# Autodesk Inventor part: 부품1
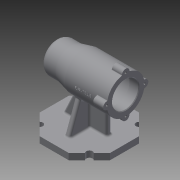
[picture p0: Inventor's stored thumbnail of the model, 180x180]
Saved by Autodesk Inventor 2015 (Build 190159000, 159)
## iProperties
Created: 2019-12
Part Number: 부품1
Material: 일반
Document SubType Name: Modeling
Designer: now
Density: 1 g/cm^3
Appearance: 기본값
Author: now
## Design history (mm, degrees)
sketch "스케치1" dims "d0" = 112
  geometry: L1 (23.196, -56)-(-23.196, -56); L2 (-23.196, -56)-(-56, -23.196); L3 (-56, -23.196)-(-56, 23.196); L4 (-56, 23.196)-(-23.196, 56); L5 (-23.196, 56)-(23.196, 56); L6 (23.196, 56)-(56, 23.196); L7 (56, 23.196)-(56, -23.196); L8 (56, -23.196)-(23.196, -56); 6 further points
  constraints: 16 end point, 3 coincident, 3 midpoint, 1 horizontal alignment, 1 vertical alignment, 20 other
extrude "돌출1" new body sketch "스케치1" distance "d1" = 10; taper "d2" = 0 deg
sketch "스케치2"
  geometry: L1 (23.196, -56)-(56, -23.196) reference; L2 (-23.196, 56)-(-56, 23.196) reference; L3 (-56, -23.196)-(-23.196, -56) reference; L4 (23.196, 56)-(56, 23.196) reference; 5 further points
  constraints: 4 midpoint
hole "구멍1" sketch "스케치2" at (-39.598, 39.598), (-39.598, -39.598), (39.598, 39.598), (39.598, -39.598) diameter "d3" = 10; stored, may be unused: countersink angle "d7" = 90 deg, drill point angle "d9" = 118 deg; dims "d4" = 6, "d5" = 4, "d6" = 2, "d8" = 8
sketch "스케치3"
  geometry: L1 (23.196, 56)-(-23.196, 56) reference; L2 (-56, 23.196)-(-56, -23.196) reference; L3 (-23.196, -56)-(23.196, -56) reference; L4 (56, -23.196)-(56, 23.196) reference; L5 (-38, 4)-(31, 4); L6 (31, 4)-(31, -4); L7 (31, -4)-(-38, -4); L8 (-38, -4)-(-38, 4); L9 (-4, 36)-(4, 36); L10 (4, 36)-(4, -36); L11 (4, -36)-(-4, -36); L12 (-4, -36)-(-4, 36); 1 further point
  constraints: 16 end point, 4 parallel, 2 horizontal, 2 perpendicular
  dimensions: "d10" = 8 distance of L9.start L9.end; "d11" = 8 distance of L5.end L6.end; "d12" = 4 distance from line of point (0, 0) L5; "d13" = 4 distance from line of point (0, 0) L12; "d14" = 18 distance between parallel lines of L2 L8; "d15" = 25 distance between parallel lines of L4 L6; "d16" = 20 distance between parallel lines of L1 L9; "d17" = 20 distance between parallel lines of L3 L11
extrude "돌출2" join sketch "스케치3" distance "d18" = 70; taper "d19" = 0 deg
feature "면 기울기1" dims angle "d20" = 25 deg
feature "면 기울기2" dims angle "d21" = 20 deg
sketch "스케치4"
  geometry: L1 (56, 0)-(-56, 0) reference; L2 (-56, 0)-(-56, 10) reference; L3 (-56, 10)-(-31, 10) reference; L4 (-31, 10)-(-31, 80) reference; L5 (-31, 80)-(5.358, 80) reference; L6 (5.358, 80)-(38, 10) reference; L7 (38, 10)-(56, 10) reference; L8 (56, 10)-(56, 0) reference; L9 (54, 80)-(-58, 80); L10 (-58, 80)-(-58, 110); L11 (-58, 110)-(9, 110); L12 (9, 110)-(29, 105); L13 (29, 105)-(54, 105); L14 (54, 105)-(54, 80); 1 further point
  constraints: 12 end point, 3 horizontal, 2 vertical
  dimensions: "d22" = 30 distance between parallel lines of L9 L11; "d23" = 80 distance between parallel lines of L1 L9; "d24" = 45 horizontal distance of L11.end L13.end; "d25" = 112 distance between parallel lines of L10 L14; "d26" = 25 distance of L13.end L12.end; "d27" = 25 distance of L13.end L9.start
revolve "회전1" sketch "스케치4" stored, may be unused: angle "d28" = 90 deg
sketch "스케치5"
  geometry: C1 r 6 at (-30, 0); C2 r 6 at (0, 30); C3 r 6 at (30, 0); C4 r 6 at (0, -30); A1 r 30 centre (0, 0) between (-30, 0) and (0, 30) reference; 1 further point
  constraints: 4 centre point, 4 point on circle
  dimensions: "d29" = 12 diameter of C1; "d30" = 12 diameter of C2; "d31" = 12 diameter of C3; "d32" = 12 diameter of C4
extrude "돌출3" join sketch "스케치5" distance "d33" = 16; taper "d34" = 0 deg
sketch "스케치6"
  geometry: A1 r 6 centre (-60, 0) between (-59.4, 5.97) and (-59.4, -5.97) reference; 1 further point
hole "구멍2" sketch "스케치6" at (-60, 0) diameter "d35" = 3.242; stored, may be unused: countersink angle "d39" = 90 deg, drill point angle "d41" = 118 deg; dims "d36" = 8, "d37" = 4, "d38" = 2, "d40" = 11.8
sketch "스케치7"
  geometry: L1 (56, 0)-(-56, 0) reference; L2 (-56, 0)-(-56, 10) reference; L3 (-56, 10)-(-31, 10) reference; L4 (-31, 10)-(-31, 50) reference; L5 (-31, 50)-(-42, 50) reference; L6 (-42, 50)-(-42, 44) reference; L7 (-42, 44)-(-58, 44) reference; L8 (-58, 44)-(-58, 48.379) reference; L9 (-58, 48.379)-(-46.2, 48.379) reference; L10 (-46.2, 48.379)-(-45.226, 50) reference; L11 (-45.226, 50)-(-46.2, 51.621) reference; L12 (-46.2, 51.621)-(-58, 51.621) reference; L13 (-58, 51.621)-(-58, 108.379) reference; L14 (-58, 108.379)-(-46.2, 108.379) reference; L15 (-46.2, 108.379)-(-45.226, 110) reference; L16 (-45.226, 110)-(-46.2, 111.621) reference; L17 (-46.2, 111.621)-(-58, 111.621) reference; L18 (-58, 111.621)-(-58, 116) reference; L19 (-58, 116)-(-42, 116) reference; L20 (-42, 116)-(-42, 110) reference; L21 (-42, 110)-(9, 110) reference; L22 (9, 110)-(29, 105) reference; L23 (29, 105)-(54, 105) reference; L24 (54, 105)-(54, 55) reference; L25 (54, 55)-(29, 55) reference; L26 (29, 55)-(18.267, 52.317) reference; L27 (18.267, 52.317)-(38, 10) reference; L28 (38, 10)-(56, 10) reference; L29 (56, 10)-(56, 0) reference; L30 (54, 80)-(-58, 80); L31 (-58, 80)-(48, 80); L32 (48, 80)-(45, 80); L33 (45, 80)-(45, 90.5); L34 (45, 90.5)-(48, 90.5); L35 (48, 90.5)-(48, 80); L36 (45, 80)-(41, 80); L37 (41, 80)-(41, 96); L38 (41, 96)-(45, 96); L39 (45, 96)-(45, 80); L40 (41, 80)-(23, 80); L41 (23, 80)-(23, 97.5); L42 (23, 97.5)-(41, 97.5); L43 (41, 97.5)-(41, 80); L44 (23, 80)-(11, 80); L45 (11, 80)-(11, 101); L46 (11, 101)-(23, 101); L47 (23, 101)-(23, 80); L48 (11, 80)-(-43, 80); L49 (-43, 80)-(-43, 104); L50 (-43, 104)-(11, 104); L51 (11, 104)-(11, 80); L52 (-43, 80)-(-58, 80); L53 (-58, 80)-(-58, 101); L54 (-58, 101)-(-43, 101); L55 (-43, 101)-(-43, 80); 1 further point
  constraints: 52 end point, 12 parallel, 6 horizontal, 6 perpendicular, 2 midpoint, 1 point on line
  dimensions: "d45" = 106 distance of L30.end L31.end; "d46" = 3 distance of L33.end L34.end; "d47" = 10.5 distance of L32.end L33.end; "d48" = 4 distance of L37.end L38.end; "d49" = 16 distance of L36.end L37.end; "d50" = 18 distance of L41.end L42.end; "d51" = 17.5 distance of L40.end L41.end; "d52" = 12 distance of L45.end L46.end; "d53" = 21 distance of L44.end L45.end; "d54" = 54 distance of L49.end L50.end; "d55" = 24 distance of L48.end L49.end; "d56" = 15 distance of L53.end L54.end; "d57" = 21 distance of L52.end L53.end
revolve "회전2" sketch "스케치7" stored, may be unused: angle "d58" = 90 deg
fillet "모깎기1" dims "d59" = 3
fillet "모깎기2" dims "d60" = 3
fillet "모깎기3" dims "d61" = 0.3
fillet "모깎기4" dims "d62" = 3
fillet "모깎기5" dims "d63" = 3
fillet "모깎기6" dims "d64" = 1
chamfer "모따기1" distance "d65" = 1; stored, may be unused: second distance "d66" = 2, angle "d67" = 45 deg
fillet "모깎기7" dims "d68" = 10
fillet "모깎기8" dims "d69" = 3
node "작업 평면1"
sketch "스케치8"
  geometry: L1 (-17.812, 2.09)-(10.029, 2.09); L2 (10.029, 2.09)-(10.029, -1.85); L3 (10.029, -1.85)-(-17.812, -1.85); L4 (-17.812, -1.85)-(-17.812, 2.09); 1 further point
  constraints: 2 other
feature "엠보싱1" sketch "스케치8" dims "d70" = 0.5, "d71" = 0
node "솔리드1"
pattern_circular "원형 패턴1" dims angle "d43" = 360 deg
node "절단 모서리 투영1"
node "절단 모서리 투영2"
